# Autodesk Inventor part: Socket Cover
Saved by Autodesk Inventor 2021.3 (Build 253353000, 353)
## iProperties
Created: 2022-08
Part Number: Socket Cover
Material: Generic
Document SubType Name: Modeling
Designer: Administrator
Density: 1 g/cm^3
Appearance: Default
Title: Socket Cover
Author: Administrator
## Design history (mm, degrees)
feature "Socket Cover"
body "Solid1"
